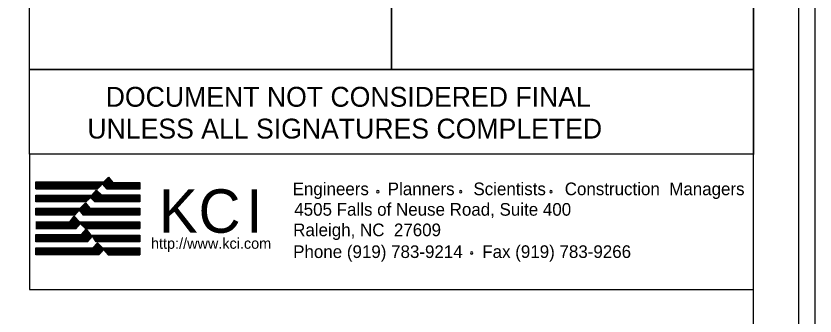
# Model space of a CAD drawing. Extents: x 2111095 to 2115970, y 670428 to 672393.
# Drawn here: x 2113046.8 to 2113267.5, y 671985.2 to 672068.3 of the extents above; entities that cross this region are included whole.
import ezdxf

# ---------------------------------------------------------------- set-up
doc = ezdxf.new("R2010")
doc.units = 0
for name, color, linetype in [('Old_Level_1', 7, 'Continuous'), ('Sheet Plot Border Inside CELL', 7, 'Continuous'), ('Sheet Plot Border Outside CELL', 7, 'Continuous'), ('Sheet Profile CELL', 7, 'Continuous'), ('Sheet Sticker Exception Certification CELL', 7, 'Continuous'), ('Sheet Typical CELL', 7, 'Continuous')]:
    doc.layers.add(name, color=color, linetype=linetype)

msp = doc.modelspace()

# ---------------------------------------------------------------- linework, layer by layer
at = {"layer": 'Old_Level_1'}
for p, q in [((2113052.21, 672022.29), (2113073.43, 672022.29)), ((2113052.21, 672022.14), (2113081, 672022.14)), ((2113052.21, 672021.99), (2113081, 672021.99)), ((2113071.1, 672022.45), (2113073.3, 672022.45)), ((2113071.24, 672022.6), (2113073.17, 672022.6)), ((2113071.4, 672022.75), (2113073.04, 672022.75)), ((2113071.55, 672022.91), (2113072.91, 672022.91)), ((2113071.68, 672023.06), (2113072.79, 672023.06)), ((2113071.83, 672023.21), (2113072.66, 672023.21)), ((2113071.97, 672023.37), (2113072.53, 672023.37)), ((2113072.13, 672023.52), (2113072.4, 672023.52)), ((2113052.21, 672021.83), (2113081, 672021.83)), ((2113052.21, 672021.68), (2113070.56, 672021.68)), ((2113052.21, 672021.52), (2113070.41, 672021.52)), ((2113052.21, 672021.36), (2113070.25, 672021.36)), ((2113052.21, 672021.21), (2113070.1, 672021.21)), ((2113052.21, 672021.06), (2113069.95, 672021.06)), ((2113052.21, 672020.9), (2113069.79, 672020.9)), ((2113052.21, 672020.75), (2113069.64, 672020.75)), ((2113052.21, 672020.6), (2113069.49, 672020.6)), ((2113052.21, 672020.44), (2113069.34, 672020.44)), ((2113068.8, 672019.83), (2113069.3, 672019.83)), ((2113068.94, 672019.98), (2113069.14, 672019.98)), ((2113070.74, 672021.68), (2113081, 672021.68)), ((2113070.89, 672021.52), (2113081, 672021.52)), ((2113071.03, 672021.36), (2113081, 672021.36)), ((2113071.18, 672021.21), (2113081, 672021.21)), ((2113071.33, 672021.06), (2113081, 672021.06)), ((2113071.47, 672020.9), (2113081, 672020.9)), ((2113071.62, 672020.75), (2113081, 672020.75)), ((2113071.76, 672020.6), (2113081, 672020.6)), ((2113071.91, 672020.44), (2113081, 672020.44)), ((2113052.21, 672018.59), (2113081, 672018.59)), ((2113052.21, 672018.44), (2113081, 672018.44)), ((2113052.21, 672018.28), (2113081, 672018.28)), ((2113052.21, 672018.13), (2113081, 672018.13)), ((2113052.21, 672017.97), (2113067.34, 672017.97)), ((2113052.21, 672017.82), (2113067.17, 672017.82)), ((2113052.21, 672017.67), (2113067, 672017.67)), ((2113067.4, 672017.97), (2113081, 672017.97)), ((2113067.56, 672017.82), (2113081, 672017.82)), ((2113067.71, 672017.67), (2113081, 672017.67)), ((2113067.83, 672018.74), (2113081, 672018.74)), ((2113067.97, 672018.9), (2113070.25, 672018.9)), ((2113068.1, 672019.06), (2113070.1, 672019.06)), ((2113068.24, 672019.2), (2113069.93, 672019.2)), ((2113068.38, 672019.37), (2113069.77, 672019.37)), ((2113068.52, 672019.52), (2113069.61, 672019.52)), ((2113068.66, 672019.67), (2113069.46, 672019.67)), ((2113052.21, 672017.51), (2113066.83, 672017.51)), ((2113052.21, 672017.36), (2113066.67, 672017.36)), ((2113052.21, 672017.21), (2113066.5, 672017.21)), ((2113052.21, 672017.05), (2113066.34, 672017.05)), ((2113052.21, 672016.9), (2113066.16, 672016.9)), ((2113064.76, 672015.38), (2113066.87, 672015.38)), ((2113064.91, 672015.53), (2113066.76, 672015.53)), ((2113065.07, 672015.69), (2113066.63, 672015.69)), ((2113065.22, 672015.84), (2113066.5, 672015.84)), ((2113065.37, 672015.99), (2113066.37, 672015.99)), ((2113065.52, 672016.15), (2113066.24, 672016.15)), ((2113065.68, 672016.3), (2113066.11, 672016.3)), ((2113065.83, 672016.46), (2113065.98, 672016.46)), ((2113067.87, 672017.51), (2113081, 672017.51)), ((2113068.02, 672017.36), (2113081, 672017.36)), ((2113068.18, 672017.21), (2113081, 672017.21)), ((2113068.33, 672017.05), (2113081, 672017.05)), ((2113068.5, 672016.9), (2113081, 672016.9)), ((2113052.21, 672014.92), (2113081, 672014.92)), ((2113052.21, 672014.76), (2113081, 672014.77)), ((2113052.21, 672014.61), (2113081, 672014.61)), ((2113052.21, 672014.46), (2113064.07, 672014.46)), ((2113052.21, 672014.3), (2113063.94, 672014.31)), ((2113052.21, 672014.15), (2113063.8, 672014.15)), ((2113052.21, 672014), (2113063.67, 672014)), ((2113052.21, 672013.84), (2113063.54, 672013.84)), ((2113052.21, 672013.68), (2113063.4, 672013.68)), ((2113052.21, 672013.53), (2113063.28, 672013.53)), ((2113052.21, 672013.37), (2113063.15, 672013.37)), ((2113052.21, 672013.22), (2113063.01, 672013.22)), ((2113061.25, 672015.07), (2113081, 672015.07)), ((2113064.27, 672014.46), (2113081, 672014.46)), ((2113064.41, 672014.31), (2113081, 672014.31)), ((2113064.54, 672014.15), (2113081, 672014.15)), ((2113064.61, 672015.23), (2113067, 672015.23)), ((2113064.68, 672014), (2113081, 672014)), ((2113064.81, 672013.84), (2113081, 672013.84)), ((2113064.94, 672013.68), (2113081, 672013.68)), ((2113065.08, 672013.53), (2113081, 672013.53)), ((2113065.21, 672013.37), (2113081, 672013.37)), ((2113065.35, 672013.22), (2113081, 672013.22)), ((2113052.21, 672011.3), (2113061.61, 672011.3)), ((2113052.21, 672011.15), (2113081, 672011.15)), ((2113052.21, 672011), (2113081, 672011)), ((2113061.61, 672011.3), (2113062.87, 672012.88)), ((2113061.61, 672011.32), (2113064.26, 672011.32)), ((2113061.74, 672011.47), (2113064.12, 672011.47)), ((2113061.85, 672011.63), (2113063.99, 672011.63)), ((2113061.98, 672011.78), (2113063.85, 672011.78)), ((2113062.1, 672011.93), (2113063.71, 672011.93)), ((2113062.23, 672012.09), (2113063.58, 672012.09)), ((2113062.36, 672012.24), (2113063.44, 672012.24)), ((2113062.48, 672012.39), (2113063.3, 672012.39)), ((2113062.61, 672012.55), (2113063.17, 672012.55)), ((2113062.72, 672012.7), (2113063.04, 672012.7)), ((2113062.85, 672012.85), (2113062.9, 672012.85)), ((2113062.87, 672012.88), (2113064.27, 672011.3)), ((2113064.27, 672011.3), (2113081, 672011.3)), ((2113081, 672011.3), (2113081, 672009.45)), ((2113052.21, 672010.85), (2113064.5, 672010.85)), ((2113052.21, 672010.69), (2113064.36, 672010.69)), ((2113052.21, 672010.54), (2113064.23, 672010.54)), ((2113052.21, 672010.39), (2113064.09, 672010.39)), ((2113052.21, 672010.23), (2113063.96, 672010.23)), ((2113052.21, 672010.08), (2113063.82, 672010.08)), ((2113052.21, 672009.93), (2113063.69, 672009.93)), ((2113052.21, 672009.77), (2113063.55, 672009.77)), ((2113052.21, 672009.62), (2113063.41, 672009.62)), ((2113052.21, 672009.47), (2113063.28, 672009.47)), ((2113063.22, 672009.39), (2113052.21, 672009.39)), ((2113064.5, 672010.85), (2113063.22, 672009.39)), ((2113064.5, 672010.85), (2113081, 672010.85)), ((2113065.95, 672009.45), (2113064.5, 672010.85)), ((2113064.66, 672010.69), (2113081, 672010.69)), ((2113064.82, 672010.54), (2113081, 672010.54)), ((2113064.98, 672010.39), (2113081, 672010.39)), ((2113065.13, 672010.23), (2113081, 672010.23)), ((2113065.29, 672010.08), (2113081, 672010.08)), ((2113065.45, 672009.93), (2113081, 672009.93)), ((2113065.61, 672009.77), (2113081, 672009.77)), ((2113065.76, 672009.62), (2113081, 672009.62)), ((2113065.8, 672008.83), (2113066.53, 672008.83)), ((2113065.93, 672009.47), (2113081, 672009.47)), ((2113065.93, 672008.99), (2113066.41, 672008.99)), ((2113081, 672009.45), (2113065.95, 672009.45)), ((2113066.05, 672009.14), (2113066.28, 672009.14)), ((2113052.21, 672007.75), (2113067.36, 672007.75)), ((2113052.21, 672007.6), (2113081, 672007.6)), ((2113052.21, 672007.44), (2113081, 672007.44)), ((2113052.21, 672007.29), (2113067.83, 672007.29)), ((2113052.21, 672007.14), (2113067.69, 672007.14)), ((2113052.21, 672006.98), (2113067.56, 672006.98)), ((2113052.21, 672006.83), (2113067.42, 672006.83)), ((2113052.21, 672006.68), (2113067.29, 672006.68)), ((2113052.21, 672006.51), (2113067.15, 672006.51)), ((2113065.02, 672007.9), (2113067.25, 672007.9)), ((2113065.15, 672008.06), (2113067.13, 672008.06)), ((2113065.28, 672008.21), (2113067.01, 672008.21)), ((2113065.41, 672008.37), (2113066.88, 672008.37)), ((2113065.54, 672008.52), (2113066.76, 672008.52)), ((2113065.67, 672008.67), (2113066.64, 672008.67)), ((2113067.87, 672007.29), (2113081, 672007.29)), ((2113067.98, 672007.14), (2113081, 672007.14)), ((2113068.09, 672006.98), (2113081, 672006.98)), ((2113068.2, 672006.83), (2113081, 672006.83)), ((2113068.31, 672006.68), (2113081, 672006.68)), ((2113068.43, 672006.51), (2113081, 672006.51)), ((2113052.21, 672006.36), (2113067.02, 672006.36)), ((2113052.21, 672006.21), (2113066.88, 672006.21)), ((2113052.21, 672006.05), (2113066.75, 672006.05)), ((2113052.21, 672005.9), (2113066.61, 672005.9)), ((2113068.2, 672004.36), (2113070.39, 672004.36)), ((2113068.34, 672004.51), (2113070.24, 672004.51)), ((2113068.49, 672004.67), (2113070.1, 672004.67)), ((2113068.53, 672006.36), (2113081, 672006.36)), ((2113068.63, 672004.82), (2113069.95, 672004.82)), ((2113068.64, 672006.21), (2113081, 672006.21)), ((2113068.76, 672006.05), (2113081, 672006.05)), ((2113068.78, 672004.97), (2113069.8, 672004.97)), ((2113068.87, 672005.9), (2113081, 672005.9)), ((2113068.92, 672005.13), (2113069.66, 672005.13)), ((2113069.07, 672005.28), (2113069.51, 672005.28)), ((2113069.21, 672005.43), (2113069.37, 672005.43)), ((2113052.21, 672004.04), (2113081, 672004.04)), ((2113052.21, 672003.89), (2113081, 672003.89)), ((2113052.21, 672003.74), (2113081, 672003.74)), ((2113052.21, 672003.58), (2113071.02, 672003.58)), ((2113052.21, 672003.43), (2113070.87, 672003.43)), ((2113052.21, 672003.28), (2113070.71, 672003.28)), ((2113052.21, 672003.12), (2113070.57, 672003.12)), ((2113052.21, 672002.97), (2113070.42, 672002.97)), ((2113052.21, 672002.82), (2113070.29, 672002.82)), ((2113052.21, 672002.66), (2113070.13, 672002.66)), ((2113052.21, 672002.51), (2113069.98, 672002.51)), ((2113052.21, 672002.36), (2113069.84, 672002.36)), ((2113068.05, 672004.2), (2113070.53, 672004.2)), ((2113071.05, 672003.58), (2113081, 672003.58)), ((2113071.18, 672003.43), (2113081, 672003.43)), ((2113071.32, 672003.28), (2113081, 672003.28)), ((2113071.45, 672003.12), (2113081, 672003.12)), ((2113071.57, 672002.97), (2113081, 672002.97)), ((2113071.71, 672002.82), (2113081, 672002.82)), ((2113071.84, 672002.66), (2113081, 672002.66)), ((2113071.98, 672002.51), (2113081, 672002.51)), ((2113072.11, 672002.36), (2113081, 672002.36)), ((2113072.25, 672002.2), (2113081, 672002.2))]:
    msp.add_line(p, q, dxfattribs=at)
for points in [[(2113052.21, 672022.33), (2113071, 672022.33), (2113072.28, 672023.68), (2113073.49, 672022.22), (2113081, 672022.22), (2113081, 672020.37), (2113071.99, 672020.37), (2113070.65, 672021.77), (2113069.29, 672020.4), (2113052.21, 672020.4)], [(2113052.21, 672018.68), (2113067.77, 672018.68), (2113069.03, 672020.09), (2113070.36, 672018.8), (2113081, 672018.8), (2113081, 672016.82), (2113068.57, 672016.82), (2113067.37, 672018), (2113066.09, 672016.82), (2113052.21, 672016.82)], [(2113052.21, 672015.08), (2113064.47, 672015.08), (2113065.92, 672016.54), (2113067.13, 672015.08), (2113081, 672015.08), (2113081, 672013.17), (2113065.39, 672013.17), (2113064.18, 672014.58), (2113062.96, 672013.17), (2113052.21, 672013.17)], [(2113052.21, 672007.76), (2113064.9, 672007.76), (2113066.17, 672009.27), (2113067.44, 672007.65), (2113081, 672007.65), (2113081, 672005.79), (2113068.94, 672005.79), (2113067.85, 672007.31), (2113066.52, 672005.79), (2113052.21, 672005.79)], [(2113052.21, 672004.11), (2113067.97, 672004.11), (2113069.29, 672005.51), (2113070.63, 672004.11), (2113081, 672004.12), (2113081, 672002.14), (2113072.3, 672002.14), (2113071.03, 672003.6), (2113069.69, 672002.2), (2113052.21, 672002.2)]]:
    msp.add_lwpolyline(points, close=True, dxfattribs=at)
for centre, start, end in [((2113146.73, 672019.64), 360, 180), ((2113169.6, 672019.64), 360, 180), ((2113194.57, 672019.64), 360, 180), ((2113146.73, 672019.64), 180, 360), ((2113169.6, 672019.64), 180, 360), ((2113194.57, 672019.64), 180, 360), ((2113172.69, 672002.71), 360, 180), ((2113172.69, 672002.71), 180, 360)]:
    msp.add_arc(centre, 0.329, start, end, dxfattribs=at)
at = {"layer": 'Sheet Plot Border Inside CELL'}
msp.add_lwpolyline([(2113263.02, 672193.58), (2111596.52, 672193.58), (2111596.52, 671138.48), (2113263.02, 671138.48)], close=True, dxfattribs=at)
at = {"layer": 'Sheet Plot Border Outside CELL'}
msp.add_lwpolyline([(2113267.52, 672216.03), (2111583.52, 672216.03), (2111583.52, 671116.03), (2113267.52, 671116.03)], close=True, dxfattribs=at)
at = {"layer": 'Sheet Profile CELL'}
for p, q in [((2113050.47, 672029.98), (2113050.5, 671992.53)), ((2113050.5, 671992.53), (2113250.52, 671992.53))]:
    msp.add_line(p, q, dxfattribs=at)
at = {"layer": 'Sheet Sticker Exception Certification CELL'}
for p, q in [((2113050.47, 672029.98), (2113050.47, 672053.48)), ((2113050.47, 672053.48), (2113250.51, 672053.48)), ((2113250.51, 672053.47), (2113250.51, 672029.97)), ((2113250.51, 672029.98), (2113050.47, 672029.98))]:
    msp.add_line(p, q, dxfattribs=at)
at = {"layer": 'Sheet Typical CELL'}
msp.add_line((2113150.52, 672165.98), (2113150.52, 672053.53), dxfattribs=at)
for points in [[(2113250.52, 672191.03), (2111750.52, 672191.03), (2111750.52, 671141.03), (2113250.52, 671141.03)], [(2113050.47, 672165.98), (2113150.52, 672165.98), (2113150.52, 672053.48), (2113050.47, 672053.48)], [(2113150.52, 672165.98), (2113250.52, 672165.98), (2113250.52, 672053.48), (2113150.52, 672053.48)]]:
    msp.add_lwpolyline(points, close=True, dxfattribs=at)

# ---------------------------------------------------------------- texts
at = {"layer": 'Old_Level_1'}
for s, height, p in [('Engineers    Planners    Scientists    Construction  Managers', 3.5, (2113123.19, 672018.67)), ('K', 12.01, (2113086.27, 672008.28)), ('C', 12.01, (2113097.19, 672008.28)), ('I', 12.01, (2113110.36, 672008.28)), ('4505 Falls of Neuse Road, Suite 400', 3.5, (2113123.65, 672012.99)), ('Raleigh, NC  27609', 3.5, (2113123.34, 672007.32)), ('http://www.kci.com', 2.9776, (2113084.07, 672003.84)), ('Phone (919) 783-9214', 3.5, (2113123.34, 672001.29)), ('Fax (919) 783-9266', 3.5, (2113175.59, 672001.3))]:
    msp.add_text(s, height=height, rotation=360, dxfattribs=at).set_placement(p)
at = {"layer": 'Sheet Sticker Exception Certification CELL'}
for s, p in [('DOCUMENT NOT CONSIDERED FINAL', (2113071.54, 672043.14)), ('UNLESS ALL SIGNATURES COMPLETED', (2113066.47, 672034.34))]:
    msp.add_text(s, height=5.5, dxfattribs=at).set_placement(p)

doc.saveas('drawing.dxf')
